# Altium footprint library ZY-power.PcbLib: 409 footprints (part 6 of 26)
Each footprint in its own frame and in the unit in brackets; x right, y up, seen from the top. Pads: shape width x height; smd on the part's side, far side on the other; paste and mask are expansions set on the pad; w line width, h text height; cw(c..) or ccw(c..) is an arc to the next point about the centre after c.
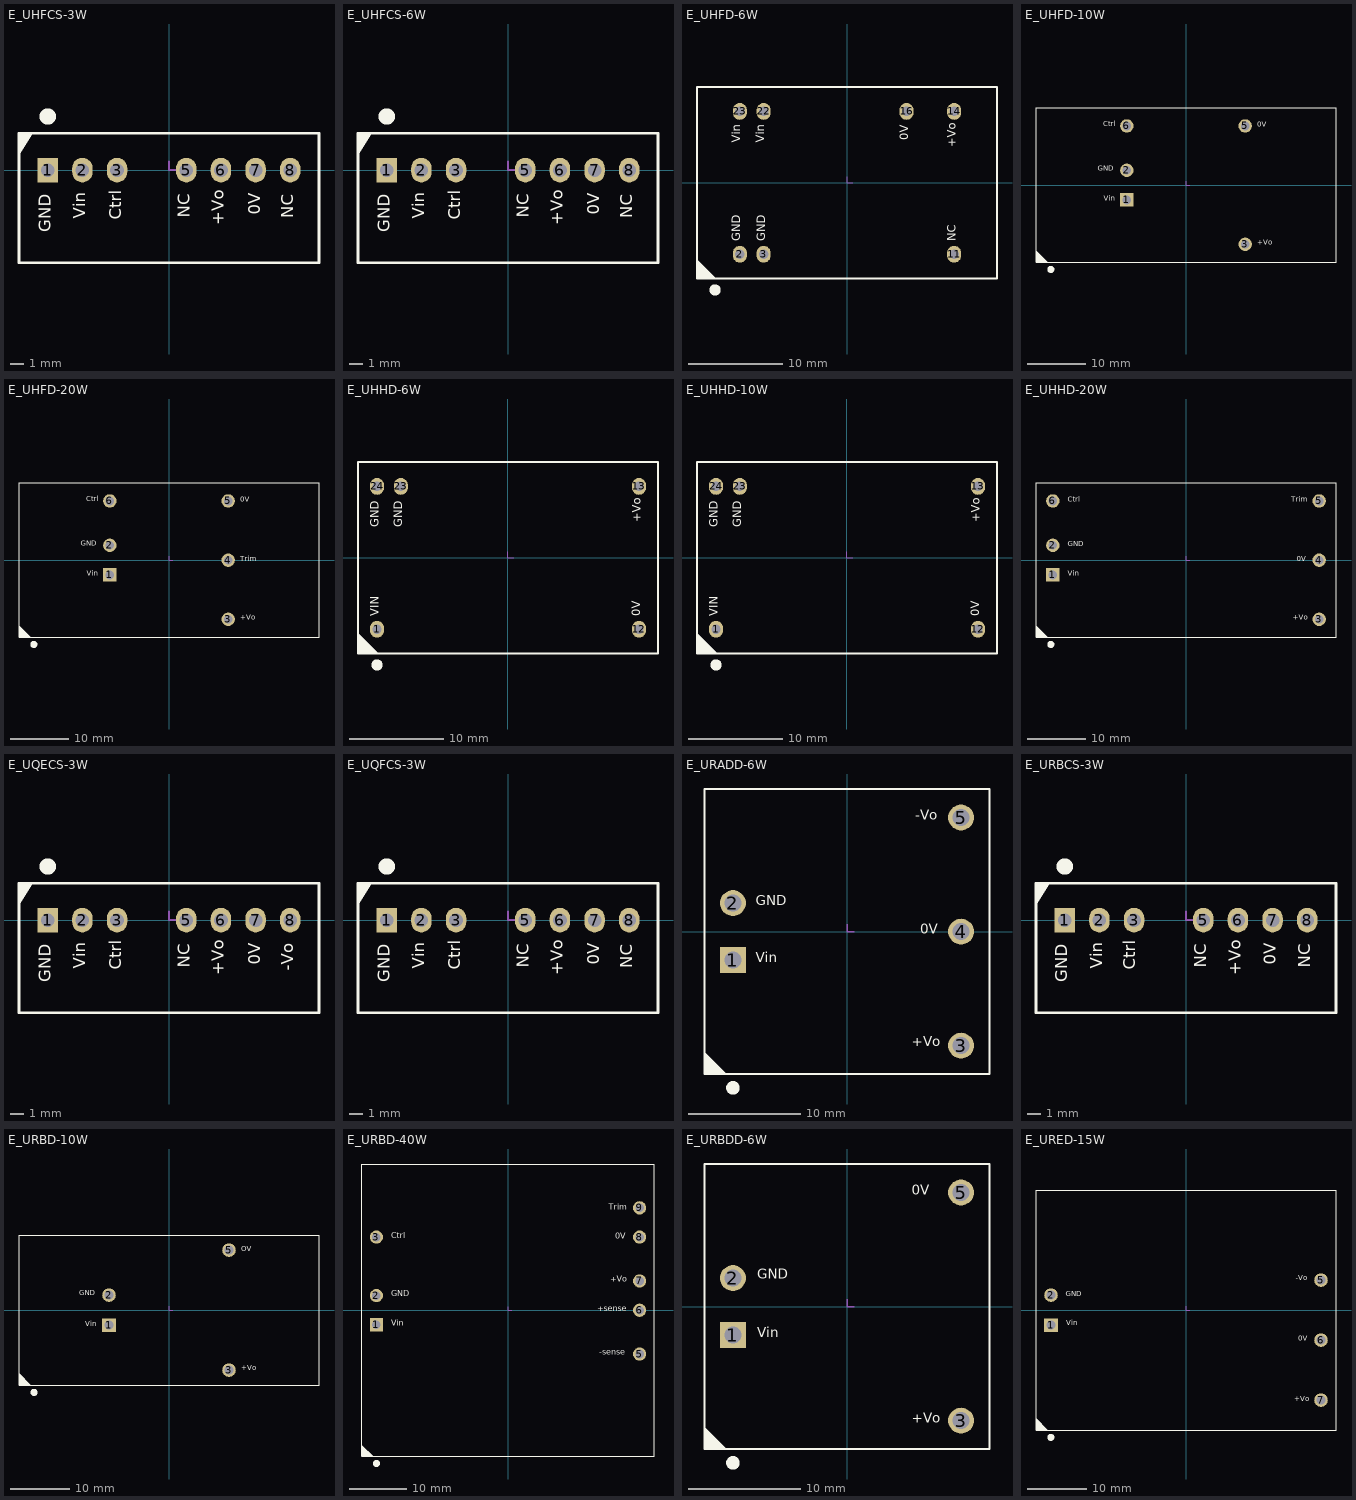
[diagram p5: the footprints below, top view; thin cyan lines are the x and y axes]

## E_UHFCS-3W [mm]
height 12
pads (7):
  rect 1.5x1.8 hole 1: 1(-8.89,0)
  oval 1.5x1.8 hole 1: 2(-6.35,0) 3(-3.81,0) 5(1.27,0) 6(3.81,0) 7(6.35,0) 8(8.89,0)
Top Overlay:
  circle w1: c-8.89,3.925 r0.1
  region: -11,1.114 -11,2.7 -10.006,2.7
  lines w0.2: -11,-6.8 -11,2.7 11,2.7 11,-6.8 -11,-6.8
  text "NC" at 9.398,-3.538 h1.52
  text "0V" at 6.985,-3.291 h1.52
  text "+Vo" at 4.318,-4.031 h1.52
  text "Vin" at -5.842,-3.563 h1.52
  text "GND" at -8.382,-4.573 h1.52
  text "Ctrl" at -3.226,-3.648 h1.52
  text "NC" at 1.803,-3.502 h1.52
Mechanical 15:
  lines w0.127: 0,0.635 0,0 0.635,0
3D body "zhenjao01.stp": height 8.36, standoff -4.08, extent 8.19,-0.12 9.59,1.48
3D body "zhenjao01.stp": height 8.36, standoff -4.08, extent 5.65,-0.12 7.05,1.48
3D body "zhenjao01.stp": height 8.36, standoff -4.08, extent 3.11,-0.12 4.51,1.48
3D body "zhenjao01.stp": height 8.36, standoff -4.08, extent 0.57,-0.12 1.97,1.48
3D body "zhenjao01.stp": height 8.36, standoff -4.08, extent -4.51,-0.12 -3.11,1.48
3D body "zhenjao01.stp": height 8.36, standoff -4.08, extent -7.05,-0.12 -5.65,1.48
3D body "zhenjao01.stp": height 8.36, standoff -4.08, extent -9.59,-0.12 -8.19,1.48
3D body: height 12, standoff 0, extent -10.93,-6.8 11,2.7

## E_UHFCS-6W [mm]
height 12
pads (7):
  rect 1.5x1.8 hole 1: 1(-8.89,0)
  oval 1.5x1.8 hole 1: 2(-6.35,0) 3(-3.81,0) 5(1.27,0) 6(3.81,0) 7(6.35,0) 8(8.89,0)
Top Overlay:
  circle w1: c-8.89,3.925 r0.1
  region: -11,1.114 -11,2.7 -10.006,2.7
  lines w0.2: -11,-6.8 -11,2.7 11,2.7 11,-6.8 -11,-6.8
  text "NC" at 9.398,-3.538 h1.52
  text "0V" at 6.985,-3.291 h1.52
  text "+Vo" at 4.318,-4.031 h1.52
  text "Vin" at -5.842,-3.563 h1.52
  text "GND" at -8.382,-4.573 h1.52
  text "Ctrl" at -3.226,-3.648 h1.52
  text "NC" at 1.803,-3.502 h1.52
Mechanical 15:
  lines w0.127: 0,0.635 0,0 0.635,0
3D body "zhenjao01.stp": height 8.36, standoff -4.08, extent 8.19,-0.12 9.59,1.48
3D body "zhenjao01.stp": height 8.36, standoff -4.08, extent 5.65,-0.12 7.05,1.48
3D body "zhenjao01.stp": height 8.36, standoff -4.08, extent 3.11,-0.12 4.51,1.48
3D body "zhenjao01.stp": height 8.36, standoff -4.08, extent 0.57,-0.12 1.97,1.48
3D body "zhenjao01.stp": height 8.36, standoff -4.08, extent -4.51,-0.12 -3.11,1.48
3D body "zhenjao01.stp": height 8.36, standoff -4.08, extent -7.05,-0.12 -5.65,1.48
3D body "zhenjao01.stp": height 8.36, standoff -4.08, extent -9.59,-0.12 -8.19,1.48
3D body: height 12, standoff 0, extent -10.93,-6.8 11,2.7

## E_UHFD-6W [mm]
height 10.2
pads (7):
  oval 1.5x1.8 hole 1: 2(-11.43,-7.62) 3(-8.89,-7.62) 11(11.43,-7.62) 14(11.43,7.62) 16(6.35,7.62) 22(-8.89,7.62) 23(-11.43,7.62)
Top Overlay:
  circle w1: c-14.072,-11.425 r0.1
  region: -16,-10.2 -14.025,-10.2 -16,-8.225
  lines w0.2: -16,-10.2 16,-10.2 16,10.2 -16,10.2 -16,-10.2
  text "0V" at 6.858,4.55 h1.52
  text "+Vo" at 11.938,3.81 h1.52
  text "NC" at 11.938,-6.223 h1.52
  text "Vin" at -8.509,4.278 h1.52
  text "Vin" at -11.049,4.278 h1.52
  text "GND" at -8.382,-6.223 h1.52
  text "GND" at -11.049,-6.223 h1.52
Mechanical 15:
  lines w0.127: 0,0.635 0,0 0.635,0
3D body: height 11, standoff 0, extent -16,-10.2 16,10.2
3D body "zhen01.stp": height 6.09, standoff -4.41, extent -11.68,7.37 -11.18,7.87
3D body "zhen01.stp": height 6.09, standoff -4.41, extent -9.14,7.37 -8.64,7.87
3D body "zhen01.stp": height 6.09, standoff -4.41, extent 6.1,7.37 6.6,7.87
3D body "zhen01.stp": height 6.09, standoff -4.41, extent 11.18,7.37 11.68,7.87
3D body "zhen01.stp": height 6.09, standoff -4.41, extent 11.18,-7.87 11.68,-7.37
3D body "zhen01.stp": height 6.09, standoff -4.41, extent -11.68,-7.87 -11.18,-7.37
3D body "zhen01.stp": height 6.09, standoff -4.41, extent -9.14,-7.87 -8.64,-7.37

## E_UHFD-10W [mm]
height 12
pads (5):
  rect 2.3x2.3 hole 1.5: 1(-10.16,-2.54)
  round 2.3 hole 1.5: 2(-10.16,2.54) 3(10.16,-10.16) 5(10.16,10.16) 6(-10.16,10.16)
Top Overlay:
  circle w1: c-23.21,-14.475 r0.1
  region: -25.75,-13.25 -23.775,-13.25 -25.75,-11.275
  lines w0.2: -25.75,-13.25 -25.75,13.25 25.75,13.25 25.75,-13.25 -25.75,-13.25
  text "+Vo" at 12.192,-10.541 h1.52
  text "0V" at 12.192,9.652 h1.52
  text "GND" at -15.113,2.159 h1.52
  text "Vin" at -14.103,-3.048 h1.52
  text "Ctrl" at -14.187,9.779 h1.52
Mechanical 15:
  lines w0.127: 0,0.635 0,0 0.635,0
3D body: height 12, standoff 0, extent -25.75,-13.25 25.75,13.25
3D body: height -1.1, standoff -6.01, extent -10.656,2.041 -9.66,3.039
3D body: height -1.1, standoff -6.01, extent -10.656,-3.039 -9.66,-2.041
3D body: height -1.1, standoff -6.01, extent -10.656,9.661 -9.66,10.659
3D body: height -1.1, standoff -6.01, extent 9.664,9.661 10.66,10.659
3D body: height -1.1, standoff -6.01, extent 9.664,-10.659 10.66,-9.661

## E_UHFD-20W [mm]
height 12
pads (6):
  rect 2.3x2.3 hole 1.5: 1(-10.16,-2.54)
  round 2.3 hole 1.5: 2(-10.16,2.54) 3(10.16,-10.16) 4(10.16,0) 5(10.16,10.16) 6(-10.16,10.16)
Top Overlay:
  circle w1: c-23.21,-14.475 r0.1
  region: -25.75,-13.25 -23.775,-13.25 -25.75,-11.275
  lines w0.2: -25.75,-13.25 25.75,-13.25 25.75,13.25 -25.75,13.25 -25.75,-13.25
  text "Ctrl" at -14.187,9.779 h1.52
  text "Trim" at 12.192,-0.508 h1.52
  text "Vin" at -14.103,-3.048 h1.52
  text "GND" at -15.113,2.159 h1.52
  text "0V" at 12.192,9.652 h1.52
  text "+Vo" at 12.192,-10.541 h1.52
Mechanical 15:
  lines w0.127: 0,0.635 0,0 0.635,0
3D body: height -1.1, standoff -6.01, extent 9.664,-0.499 10.66,0.499
3D body: height -1.1, standoff -6.01, extent 9.664,-10.659 10.66,-9.661
3D body: height -1.1, standoff -6.01, extent 9.664,9.661 10.66,10.659
3D body: height -1.1, standoff -6.01, extent -10.656,9.661 -9.66,10.659
3D body: height -1.1, standoff -6.01, extent -10.656,-3.039 -9.66,-2.041
3D body: height -1.1, standoff -6.01, extent -10.656,2.041 -9.66,3.039
3D body: height 12, standoff 0, extent -25.75,-13.25 25.75,13.25

## E_UHHD-6W [mm]
height 12.6
pads (5):
  oval 1.5x1.8 hole 1: 1(-13.97,-7.62) 12(13.97,-7.62) 13(13.97,7.62) 23(-11.43,7.62) 24(-13.97,7.62)
Top Overlay:
  circle w1: c-13.97,-11.425 r0.1
  region: -15.898,-10.103 -13.923,-10.103 -15.898,-8.128
  lines w0.2: -16,-10.2 16,-10.2 16,10.2 -16,10.2 -16,-10.2
  text "+Vo" at 14.478,3.811 h1.52
  text "0V" at 14.453,-6.223 h1.52
  text "VIN" at -13.482,-6.222 h1.52
  text "GND" at -13.479,3.266 h1.52
  text "GND" at -10.939,3.266 h1.52
Mechanical 15:
  lines w0.127: 0,0.635 0,0 0.635,0
3D body "zhen01.stp": height 6.09, standoff -4.41, extent 13.72,7.37 14.22,7.87
3D body "zhen01.stp": height 6.09, standoff -4.41, extent 13.72,-7.87 14.22,-7.37
3D body: height 12.6, standoff 0, extent -16,-10.2 16,10.2
3D body "zhen01.stp": height 6.09, standoff -4.41, extent -11.68,7.37 -11.18,7.87
3D body "zhen01.stp": height 6.09, standoff -4.41, extent -14.22,-7.87 -13.72,-7.37
3D body "zhen01.stp": height 6.09, standoff -4.41, extent -14.22,7.37 -13.72,7.87

## E_UHHD-10W [mm]
height 12.6
pads (5):
  oval 1.5x1.8 hole 1: 1(-13.97,-7.62) 12(13.97,-7.62) 13(13.97,7.62) 23(-11.43,7.62) 24(-13.97,7.62)
Top Overlay:
  circle w1: c-13.97,-11.425 r0.1
  region: -15.898,-10.103 -13.923,-10.103 -15.898,-8.128
  lines w0.2: -16,-10.2 -16,10.2 16,10.2 16,-10.2 -16,-10.2
  text "GND" at -10.939,3.266 h1.52
  text "GND" at -13.479,3.266 h1.52
  text "VIN" at -13.482,-6.221 h1.52
  text "0V" at 14.453,-6.223 h1.52
  text "+Vo" at 14.478,3.811 h1.52
Mechanical 15:
  lines w0.127: 0,0.635 0,0 0.635,0
3D body "zhen01.stp": height 6.09, standoff -4.41, extent -14.22,7.37 -13.72,7.87
3D body "zhen01.stp": height 6.09, standoff -4.41, extent -14.22,-7.87 -13.72,-7.37
3D body "zhen01.stp": height 6.09, standoff -4.41, extent -11.68,7.37 -11.18,7.87
3D body: height 12.6, standoff 0, extent -16,-10.2 16,10.2
3D body "zhen01.stp": height 6.09, standoff -4.41, extent 13.72,-7.87 14.22,-7.37
3D body "zhen01.stp": height 6.09, standoff -4.41, extent 13.72,7.37 14.22,7.87

## E_UHHD-20W [mm]
height 12
pads (6):
  rect 2.3x2.3 hole 1.5: 1(-22.86,-2.54)
  round 2.3 hole 1.5: 2(-22.86,2.54) 3(22.86,-10.16) 4(22.86,0) 5(22.86,10.16) 6(-22.86,10.16)
Top Overlay:
  circle w1: c-23.21,-14.475 r0.1
  region: -25.75,-13.25 -23.775,-13.25 -25.75,-11.275
  lines w0.2: -25.75,-13.25 -25.75,13.25 25.75,13.25 25.75,-13.25 -25.75,-13.25
  text "+Vo" at 18.303,-10.541 h1.52
  text "GND" at -20.321,2.059 h1.52
  text "Vin" at -20.32,-3.018 h1.52
  text "Ctrl" at -20.321,9.679 h1.52
  text "Trim" at 18.035,9.652 h1.52
  text "0V" at 19.041,-0.508 h1.52
Mechanical 15:
  lines w0.127: 0,0.635 0,0 0.635,0
3D body: height -1.1, standoff -6.01, extent -23.356,9.661 -22.36,10.659
3D body: height 12, standoff 0, extent -25.75,-13.25 25.75,13.25
3D body: height -1.1, standoff -6.01, extent -23.356,2.041 -22.36,3.039
3D body: height -1.1, standoff -6.01, extent -23.356,-3.039 -22.36,-2.041
3D body: height -1.1, standoff -6.01, extent 22.364,-10.659 23.36,-9.661
3D body: height -1.1, standoff -6.01, extent 22.364,-0.499 23.36,0.499
3D body: height -1.1, standoff -6.01, extent 22.364,9.661 23.36,10.659

## E_UQECS-3W [mm]
height 12
pads (7):
  rect 1.5x1.8 hole 1: 1(-8.89,0)
  oval 1.5x1.8 hole 1: 2(-6.35,0) 3(-3.81,0) 5(1.27,0) 6(3.81,0) 7(6.35,0) 8(8.89,0)
Top Overlay:
  circle w1: c-8.89,3.925 r0.1
  region: -11,1.114 -11,2.7 -10.006,2.7
  lines w0.2: -11,-6.8 11,-6.8 11,2.7 -11,2.7 -11,-6.8
  text "NC" at 1.803,-3.501 h1.52
  text "Ctrl" at -3.226,-3.648 h1.52
  text "GND" at -8.382,-4.573 h1.52
  text "Vin" at -5.842,-3.563 h1.52
  text "+Vo" at 4.318,-4.03 h1.52
  text "0V" at 6.985,-3.291 h1.52
  text "-Vo" at 9.398,-3.72 h1.52
Mechanical 15:
  lines w0.127: 0,0.635 0,0 0.635,0
3D body: height 12, standoff 0, extent -11,-6.8 11,2.7
3D body "zhenjao01.stp": height 8.36, standoff -4.08, extent -9.59,-0.12 -8.19,1.48
3D body "zhenjao01.stp": height 8.36, standoff -4.08, extent -7.05,-0.12 -5.65,1.48
3D body "zhenjao01.stp": height 8.36, standoff -4.08, extent -4.51,-0.12 -3.11,1.48
3D body "zhenjao01.stp": height 8.36, standoff -4.08, extent 0.57,-0.12 1.97,1.48
3D body "zhenjao01.stp": height 8.36, standoff -4.08, extent 3.11,-0.12 4.51,1.48
3D body "zhenjao01.stp": height 8.36, standoff -4.08, extent 5.65,-0.12 7.05,1.48
3D body "zhenjao01.stp": height 8.36, standoff -4.08, extent 8.19,-0.12 9.59,1.48

## E_UQFCS-3W [mm]
height 12
pads (7):
  rect 1.5x1.8 hole 1: 1(-8.89,0)
  oval 1.5x1.8 hole 1: 2(-6.35,0) 3(-3.81,0) 5(1.27,0) 6(3.81,0) 7(6.35,0) 8(8.89,0)
Top Overlay:
  circle w1: c-8.89,3.925 r0.1
  region: -11,1.114 -11,2.7 -10.006,2.7
  lines w0.2: -11,-6.8 -11,2.7 11,2.7 11,-6.8 -11,-6.8
  text "NC" at 9.398,-3.538 h1.52
  text "0V" at 6.985,-3.291 h1.52
  text "+Vo" at 4.318,-4.031 h1.52
  text "Vin" at -5.842,-3.563 h1.52
  text "GND" at -8.382,-4.573 h1.52
  text "Ctrl" at -3.226,-3.648 h1.52
  text "NC" at 1.803,-3.502 h1.52
Mechanical 15:
  lines w0.127: 0,0.635 0,0 0.635,0
3D body "zhenjao01.stp": height 8.36, standoff -4.08, extent 8.19,-0.12 9.59,1.48
3D body "zhenjao01.stp": height 8.36, standoff -4.08, extent 5.65,-0.12 7.05,1.48
3D body "zhenjao01.stp": height 8.36, standoff -4.08, extent 3.11,-0.12 4.51,1.48
3D body "zhenjao01.stp": height 8.36, standoff -4.08, extent 0.57,-0.12 1.97,1.48
3D body "zhenjao01.stp": height 8.36, standoff -4.08, extent -4.51,-0.12 -3.11,1.48
3D body "zhenjao01.stp": height 8.36, standoff -4.08, extent -7.05,-0.12 -5.65,1.48
3D body "zhenjao01.stp": height 8.36, standoff -4.08, extent -9.59,-0.12 -8.19,1.48
3D body: height 12, standoff 0, extent -11,-6.8 11,2.7

## E_URADD-6W [mm]
height 11.7
pads (5):
  rect 2.3x2.3 hole 1.5: 1(-10.16,-2.54)
  round 2.3 hole 1.5: 2(-10.16,2.54) 3(10.16,-10.16) 4(10.16,0) 5(10.16,10.16)
Top Overlay:
  circle w1: c-10.16,-13.925 r0.1
  region: -12.7,-12.7 -10.725,-12.7 -12.7,-10.725
  lines w0.2: -12.7,-12.7 12.7,-12.7 12.7,12.7 -12.7,12.7 -12.7,-12.7
  text "+Vo" at 5.764,-10.541 h1.52
  text "-Vo" at 6.076,9.652 h1.52
  text "0V" at 6.504,-0.508 h1.52
  text "GND" at -8.139,2.032 h1.52
  text "Vin" at -8.137,-3.048 h1.52
Mechanical 15:
  lines w0.127: 0,0.635 0,0 0.635,0

## E_URBCS-3W [mm]
height 12
pads (7):
  rect 1.5x1.8 hole 1: 1(-8.89,0)
  oval 1.5x1.8 hole 1: 2(-6.35,0) 3(-3.81,0) 5(1.27,0) 6(3.81,0) 7(6.35,0) 8(8.89,0)
Top Overlay:
  circle w1: c-8.89,3.925 r0.1
  region: -11,1.114 -11,2.7 -10.006,2.7
  lines w0.2: -11,-6.8 11,-6.8 11,2.7 -11,2.7 -11,-6.8
  text "Vin" at -5.834,-3.562 h1.52
  text "Ctrl" at -3.421,-3.646 h1.52
  text "NC" at 1.786,-3.501 h1.52
  text "+Vo" at 4.326,-4.03 h1.52
  text "0V" at 6.866,-3.29 h1.52
  text "GND" at -8.399,-4.572 h1.52
  text "NC" at 9.406,-3.501 h1.52
Mechanical 15:
  lines w0.127: 0,0.635 0,0 0.635,0
3D body "zhenjao01.stp": height 8.36, standoff -4.08, extent 8.19,-1.48 9.59,0.12
3D body "zhenjao01.stp": height 8.36, standoff -4.08, extent -9.59,-1.48 -8.19,0.12
3D body "zhenjao01.stp": height 8.36, standoff -4.08, extent -7.05,-1.48 -5.65,0.12
3D body "zhenjao01.stp": height 8.36, standoff -4.08, extent -4.51,-1.48 -3.11,0.12
3D body "zhenjao01.stp": height 8.36, standoff -4.08, extent 0.57,-1.48 1.97,0.12
3D body "zhenjao01.stp": height 8.36, standoff -4.08, extent 3.11,-1.48 4.51,0.12
3D body "zhenjao01.stp": height 8.36, standoff -4.08, extent 5.65,-1.48 7.05,0.12
3D body: height 12.2, standoff 0, extent -11,-6.8 11,2.7

## E_URBD-10W [mm]
height 12.7
pads (4):
  rect 2.3x2.3 hole 1.5: 1(-10.16,-2.54)
  round 2.3 hole 1.5: 2(-10.16,2.54) 3(10.16,-10.16) 5(10.16,10.16)
Top Overlay:
  circle w1: c-22.86,-13.925 r0.1
  region: -25.4,-12.7 -23.425,-12.7 -25.4,-10.725
  lines w0.2: -25.4,-12.7 -25.4,12.7 25.4,12.7 25.4,-12.7 -25.4,-12.7
  text "+Vo" at 12.192,-10.541 h1.52
  text "OV" at 12.192,9.652 h1.52
  text "GND" at -15.189,2.159 h1.52
  text "Vin" at -14.179,-3.048 h1.52
Mechanical 15:
  lines w0.127: 0,0.635 0,0 0.635,0

## E_URBD-40W [mm]
height 11.2
pads (8):
  rect 2.3x2.3 hole 1.5: 1(-22.86,-2.54)
  round 2.3 hole 1.5: 2(-22.86,2.54) 3(-22.86,12.7) 5(22.86,-7.62) 6(22.86,0) 7(22.86,5.08) 8(22.86,12.7) 9(22.86,17.78)
Top Overlay:
  circle w1: c-22.86,-26.625 r0.1
  region: -25.4,-25.4 -23.425,-25.4 -25.4,-23.425
  lines w0.2: -25.4,-25.4 25.4,-25.4 25.4,25.4 -25.4,25.4 -25.4,-25.4
  text "Trim" at 17.475,17.145 h1.78
  text "Ctrl" at -20.322,12.194 h1.78
  text "-sense" at 15.858,-8.128 h1.78
  text "+sense" at 15.494,-0.508 h1.78
  text "Vin" at -20.32,-3.046 h1.78
  text "GND" at -20.322,2.034 h1.78
  text "0V" at 18.651,12.065 h1.78
  text "+Vo" at 17.787,4.572 h1.78
Mechanical 15:
  lines w0.127: 0,0.635 0,0 0.635,0

## E_URBDD-6W [mm]
height 11.7
pads (4):
  rect 2.3x2.3 hole 1.5: 1(-10.16,-2.54)
  round 2.3 hole 1.5: 2(-10.16,2.54) 3(10.16,-10.16) 5(10.16,10.16)
Top Overlay:
  circle w1: c-10.16,-13.925 r0.1
  region: -12.7,-12.7 -10.725,-12.7 -12.7,-10.725
  lines w0.2: -12.7,-12.7 12.7,-12.7 12.7,12.7 -12.7,12.7 -12.7,-12.7
  text "+Vo" at 5.764,-10.668 h1.52
  text "0V" at 5.764,9.652 h1.52
  text "GND" at -8.012,2.159 h1.52
  text "Vin" at -8.01,-3.048 h1.52
Mechanical 15:
  lines w0.127: 0,0.635 0,0 0.635,0

## E_URED-15W [mm]
height 13.5
pads (5):
  rect 2.3x2.3 hole 1.5: 1(-22.86,-2.54)
  round 2.3 hole 1.5: 2(-22.86,2.54) 5(22.86,5.08) 6(22.86,-5.08) 7(22.86,-15.24)
Top Overlay:
  circle w1: c-22.887,-21.545 r0.1
  region: -25.4,-20.32 -23.425,-20.32 -25.4,-18.345
  lines w0.2: -25.4,-20.32 25.4,-20.32 25.4,20.32 -25.4,20.32 -25.4,-20.32
  text "-Vo" at 18.613,4.699 h1.52
  text "Vin" at -20.32,-2.921 h1.52
  text "GND" at -20.321,2.032 h1.52
  text "0V" at 19.041,-5.524 h1.52
  text "+Vo" at 18.301,-15.748 h1.52
Mechanical 15:
  lines w0.127: 0,0.635 0,0 0.635,0
3D body "E24120URED-15W.stp": height 14.3, standoff -5.6, extent -25.4,-20.32 25.4,20.28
